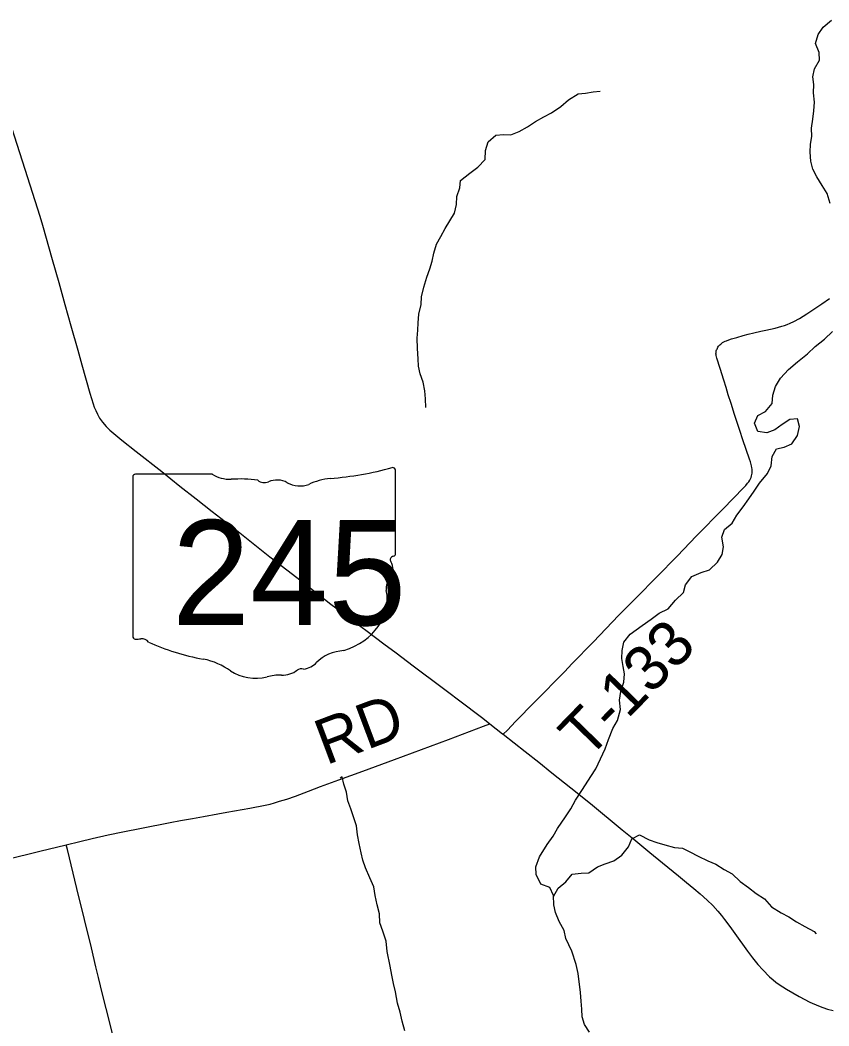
# Model space of a CAD drawing. Extents: x 0 to 1101, y 0 to 440.
# Drawn here: x 844.169 to 845.184, y 374.552 to 375.815 of the extents above; entities that cross this region are included whole.
import ezdxf

# ---------------------------------------------------------------- set-up
doc = ezdxf.new("R2010")
doc.units = 0
for name, color, linetype in [('GM_X_County_Road', 7, 'Continuous'), ('GM_X_County_Road_Text', 7, 'Continuous'), ('GM_X_Minor_River', 7, 'Continuous'), ('GM_X_State_Location', 7, 'Continuous'), ('GM_X_State_Route', 7, 'Continuous'), ('GM_X_State_Shield', 7, 'Continuous'), ('GM_X_Township_Road', 7, 'Continuous'), ('GM_X_Township_Road_Text', 7, 'Continuous')]:
    doc.layers.add(name, color=color, linetype=linetype)

msp = doc.modelspace()

# ---------------------------------------------------------------- linework, layer by layer
at = {"layer": 'GM_X_County_Road'}
for points in [[(844.2269, 374.7791), (844.2439, 374.7832), (844.2596, 374.7871), (844.2795, 374.7916), (844.2978, 374.7953), (844.3215, 374.8), (844.3575, 374.8072), (844.3703, 374.8097), (844.3855, 374.8124), (844.399, 374.8149), (844.4173, 374.8182), (844.4283, 374.82), (844.4571, 374.825), (844.4766, 374.829), (844.4827, 374.8304), (844.4881, 374.8319), (844.4947, 374.8338), (844.5036, 374.8366), (844.5148, 374.8404), (844.5311, 374.8465), (844.5462, 374.8522), (844.5689, 374.8607), (844.5993, 374.8717), (844.6389, 374.8862), (844.7066, 374.9116), (844.7505, 374.9282), (844.7584, 374.9312)], [(843.6675, 374.6391), (843.6723, 374.6421), (843.676, 374.6441), (843.6783, 374.6452), (843.6812, 374.6464), (843.6836, 374.6473), (843.6862, 374.6481), (843.6934, 374.6502), (843.6999, 374.6518), (843.7119, 374.6549), (843.73, 374.6593), (843.7837, 374.6721), (843.8399, 374.6857), (843.8774, 374.6945), (843.9257, 374.7062), (843.9721, 374.7179), (843.9992, 374.7246), (844.0312, 374.7323), (844.0959, 374.7475), (844.1515, 374.7608), (844.1938, 374.771), (844.2269, 374.7791)]]:
    msp.add_lwpolyline(points, dxfattribs=at)
at = {"layer": 'GM_X_Minor_River'}
for points in [[(845.1856, 375.5847), (845.1819, 375.5973), (845.1759, 375.6072), (845.1691, 375.618), (845.1639, 375.6276), (845.1613, 375.6379), (845.1607, 375.6489), (845.1611, 375.6592), (845.1627, 375.6687), (845.1625, 375.679), (845.1641, 375.6904), (845.1653, 375.7011), (845.1662, 375.7118), (845.1648, 375.7236), (845.1652, 375.7339), (845.1638, 375.7438), (845.1662, 375.7537), (845.1724, 375.7647), (845.1721, 375.7742), (845.1672, 375.7857), (845.1707, 375.7967), (845.1769, 375.8062), (845.1873, 375.8149)], [(844.6781, 375.3285), (844.6778, 375.3392), (844.6771, 375.3495), (844.675, 375.3602), (844.6712, 375.3705), (844.669, 375.3801), (844.6684, 375.3896), (844.6677, 375.4026), (844.6675, 375.4155), (844.6683, 375.4254), (844.6684, 375.4349), (844.6693, 375.4456), (844.6724, 375.4578), (844.6729, 375.4673), (844.6756, 375.4795), (844.6796, 375.492), (844.6831, 375.5027), (844.6862, 375.5122), (844.6882, 375.522), (844.6914, 375.5335), (844.6972, 375.5433), (844.7026, 375.5532), (844.7084, 375.563), (844.7142, 375.5725), (844.7165, 375.5835), (844.717, 375.5934), (844.7209, 375.6041), (844.7218, 375.6136), (844.7333, 375.6226), (844.7436, 375.6302), (844.7525, 375.64), (844.7533, 375.6511), (844.7565, 375.6621), (844.7661, 375.6704), (844.7756, 375.6711), (844.7851, 375.671), (844.7954, 375.6751), (844.8057, 375.6807), (844.8157, 375.6875), (844.8264, 375.6935), (844.836, 375.6984), (844.8475, 375.7066), (844.8574, 375.7146), (844.8693, 375.7221), (844.8788, 375.7231), (844.8884, 375.725), (844.8971, 375.7256)], [(844.9186, 374.9351), (844.9226, 374.9492), (844.9215, 374.961), (844.9228, 374.9716), (844.9267, 374.9834), (844.9275, 374.9937), (844.9261, 375.0032), (844.9243, 375.0131), (844.9247, 375.0234), (844.9267, 375.0337), (844.9348, 375.0439), (844.9498, 375.0544), (844.9609, 375.0627), (844.9712, 375.0699), (844.9823, 375.0755), (844.9916, 375.0864), (845.0015, 375.0959), (845.0043, 375.1058), (845.012, 375.116), (845.0238, 375.1212), (845.0342, 375.1245), (845.0445, 375.1343), (845.0503, 375.1438), (845.0519, 375.1533), (845.0497, 375.1655), (845.0533, 375.175), (845.0629, 375.1833), (845.0687, 375.1932), (845.0764, 375.2038), (845.0837, 375.2136), (845.0902, 375.2235), (845.0972, 375.2333), (845.1072, 375.2454), (845.1115, 375.2553), (845.1131, 375.2667), (845.1185, 375.2766), (845.128, 375.2784), (845.1376, 375.2829), (845.1449, 375.2931), (845.1473, 375.3045), (845.1447, 375.3141), (845.1352, 375.3134), (845.1256, 375.307), (845.1161, 375.3002), (845.1061, 375.2965), (845.0951, 375.2981), (845.0906, 375.3085), (845.0949, 375.3183), (845.1045, 375.3232), (845.1129, 375.3334), (845.1138, 375.3437), (845.1173, 375.3547), (845.1235, 375.3653), (845.1335, 375.3759), (845.1446, 375.3857), (845.1573, 375.3959), (845.1669, 375.4049), (845.1787, 375.414), (845.1887, 375.4238)], [(844.8835, 374.5439), (844.8775, 374.5535), (844.8745, 374.5631), (844.8739, 374.5726), (844.8732, 374.5829), (844.8725, 374.5935), (844.8693, 374.6175), (844.8668, 374.629), (844.8616, 374.6458), (844.8541, 374.6615), (844.8519, 374.6714), (844.8455, 374.6829), (844.8411, 374.6943), (844.8389, 374.7039), (844.8386, 374.7157), (844.8337, 374.7256), (844.8224, 374.7299), (844.8168, 374.7418), (844.8161, 374.7517), (844.8208, 374.7642), (844.8304, 374.7797), (844.8381, 374.79), (844.8435, 374.7998), (844.8536, 374.8142), (844.8601, 374.8244), (844.8659, 374.8354), (844.8748, 374.8487), (844.8852, 374.8649), (844.8914, 374.8748), (844.9035, 374.8998), (844.9077, 374.9116), (844.9128, 374.9252), (844.9186, 374.9351)], [(844.652, 374.5457), (844.6487, 374.5575), (844.6458, 374.5689), (844.6425, 374.5804), (844.6403, 374.5945), (844.6377, 374.6052), (844.6355, 374.6155), (844.6334, 374.6269), (844.6297, 374.6452), (844.6283, 374.6582), (844.6242, 374.6708), (844.6205, 374.6811), (844.6199, 374.6925), (844.6173, 374.7036), (844.6147, 374.7154), (844.6129, 374.7265), (844.6081, 374.7376), (844.6025, 374.7502), (844.5991, 374.7597), (844.5969, 374.7693), (844.5944, 374.7807), (844.5926, 374.7918), (844.5912, 374.8032), (844.5878, 374.8131), (844.5841, 374.8242), (844.5804, 374.8342), (844.5786, 374.8452), (844.5753, 374.8552), (844.5731, 374.8647), (844.5708, 374.8628)], [(844.8386, 374.7143), (844.8444, 374.7248), (844.854, 374.7327), (844.8621, 374.7425), (844.8731, 374.7436), (844.883, 374.7438), (844.8937, 374.7514), (844.9033, 374.7551), (844.9144, 374.7592), (844.9243, 374.7663), (844.9324, 374.7765), (844.9367, 374.7868), (844.9463, 374.7916), (844.9584, 374.7854), (844.9683, 374.7819), (844.9781, 374.7791), (844.9903, 374.776), (845.0002, 374.7751), (845.0097, 374.7705), (845.0199, 374.765), (845.032, 374.7592), (845.0423, 374.7549), (845.0525, 374.748), (845.0627, 374.7429), (845.0729, 374.7329), (845.0831, 374.7256), (845.0929, 374.7179), (845.1035, 374.7113), (845.1122, 374.7013), (845.1243, 374.6936), (845.1338, 374.6886), (845.1436, 374.6824), (845.1539, 374.6766), (845.1656, 374.6704), (845.1683, 374.6673)]]:
    msp.add_lwpolyline(points, dxfattribs=at)
at = {"layer": 'GM_X_State_Route'}
msp.add_lwpolyline([(844.1582, 375.6802), (844.1748, 375.6276), (844.1936, 375.5686), (844.1969, 375.5574), (844.2091, 375.5144), (844.2175, 375.4852), (844.2251, 375.4577), (844.2328, 375.4308), (844.2414, 375.4003), (844.2465, 375.3818), (844.2565, 375.3465), (844.2606, 375.3328), (844.2621, 375.3286), (844.2638, 375.3246), (844.2659, 375.3199), (844.2688, 375.3151), (844.2723, 375.3099), (844.2768, 375.3046), (844.2817, 375.2998), (844.2864, 375.2957), (844.2966, 375.2875), (844.3146, 375.2732), (844.3468, 375.2478), (844.3696, 375.2296), (844.3901, 375.2135), (844.4101, 375.1977), (844.4425, 375.1725), (844.4825, 375.141), (844.511, 375.1189), (844.5291, 375.1048), (844.5429, 375.0941), (844.5591, 375.0816), (844.5744, 375.0699), (844.5847, 375.062), (844.6027, 375.0487), (844.6256, 375.0316), (844.6411, 375.0201), (844.6625, 375.0041), (844.6987, 374.9768), (844.7274, 374.955), (844.7413, 374.9445), (844.7496, 374.9381), (844.7584, 374.9312), (844.7746, 374.9186), (844.7754, 374.918), (844.8029, 374.8963), (844.82, 374.8828), (844.8365, 374.8697), (844.8604, 374.8508), (844.885, 374.8309), (844.9247, 374.798), (844.9392, 374.7862), (844.9593, 374.7697), (844.9752, 374.7567), (844.9953, 374.7401), (845.0054, 374.7318), (845.0146, 374.7244), (845.0226, 374.7176), (845.0314, 374.7098), (845.0385, 374.7029), (845.0446, 374.696), (845.0493, 374.6902), (845.0532, 374.6854), (845.0598, 374.6764), (845.066, 374.6679), (845.082, 374.6457), (845.0884, 374.6372), (845.0951, 374.629), (845.1012, 374.622), (845.1096, 374.6135), (845.1141, 374.6095), (845.1176, 374.6066), (845.1217, 374.6036), (845.131, 374.5978), (845.1389, 374.5932), (845.1468, 374.5888), (845.1601, 374.5817), (845.1709, 374.5768), (845.1764, 374.5748), (845.1822, 374.5729), (845.1894, 374.571)], dxfattribs=at)
at = {"layer": 'GM_X_State_Shield'}
for p, q in [((844.6401, 375.1449), (844.6401, 375.2496)), ((844.3105, 375.2412), (844.3105, 375.041)), ((844.4103, 375.2446), (844.3137, 375.2446)), ((844.64, 375.1449), (844.6401, 375.1449))]:
    msp.add_line(p, q, dxfattribs=at)
for centre, major_axis, start_param, end_param in [((844.5227, 375.5174), (0.3495, 0), 4.814394, 5.042369), ((844.6364, 375.25), (0.00367, 0), 6.141152, 7.989035), ((844.3143, 375.2416), (0.00382, 0), 1.712693, 3.28349), ((844.4332, 375.2678), (0.037, 0), 4.042523, 4.731795), ((844.4455, 375.1322), (0.133, 0), 1.404758, 1.657858), ((844.4757, 375.2426), (0.0107, 0), 3.836095, 5.185415), ((844.4914, 375.2195), (0.0222, 0), 0.950623, 2.079405), ((844.5201, 375.2512), (0.0267, 0), 4.081561, 5.145723), ((844.5673, 375.1835), (0.0703, 0), 1.699011, 2.107814), ((844.6362, 375.1445), (0.00393, 0), 5.05454, 6.418171), ((844.6392, 375.1372), (0.00568, 0), 1.883978, 3.671073), ((844.6031, 375.1239), (0.0341, 0), 5.934695, 6.695948), ((844.6532, 375.1011), (0.0248, 0), 2.387724, 3.262537), ((844.5423, 375.0877), (0.0874, 0), 5.101752, 6.440018), ((844.3143, 375.0406), (0.00385, 0), 3.00124, 4.508301), ((844.3149, 375.0611), (0.0294, 0), 4.665946, 4.897461), ((844.3209, 375.0295), (0.0106, 0), 0.519207, 1.627899), ((844.4547, 375.2093), (0.2524, 0), 4.195997, 4.488961), ((844.5791, 374.9848), (0.0479, 0), 1.647645, 2.488434), ((844.3795, 374.9511), (0.079, 0), 0.823519, 1.323587), ((844.5185, 375.0216), (0.0282, 0), 4.937069, 5.64225), ((844.4649, 375.0285), (0.0501, 0), 4.026481, 4.996735), ((844.4975, 375.0135), (0.0267, 0), 4.691044, 5.507374), ((844.5217, 374.9941), (0.00752, 0), 1.147584, 2.315152), ((844.4938, 374.9593), (0.0412, 0), 1.495662, 1.94098)]:
    msp.add_ellipse(centre, major_axis=major_axis, ratio=0.8, start_param=start_param, end_param=end_param, dxfattribs=at)
at = {"layer": 'GM_X_Township_Road'}
for points in [[(844.7754, 374.918), (844.7806, 374.9233), (844.7908, 374.9339), (844.8151, 374.9588), (844.8522, 374.9964), (844.8621, 375.0067), (844.8881, 375.0335), (844.9206, 375.0677), (844.9425, 375.0897), (844.9935, 375.1415), (845.0181, 375.167), (845.0511, 375.2008), (845.0775, 375.228), (845.0798, 375.2306), (845.082, 375.2332), (845.0835, 375.2352), (845.0849, 375.2372), (845.0857, 375.2388), (845.0865, 375.2405), (845.0871, 375.2424), (845.0876, 375.2443), (845.0878, 375.2459), (845.0879, 375.2474), (845.0878, 375.249), (845.0877, 375.2508), (845.0874, 375.2527), (845.0871, 375.255), (845.0865, 375.257), (845.0856, 375.2602), (845.0845, 375.2635), (845.0762, 375.2876), (845.0722, 375.2994), (845.0658, 375.3195), (845.0614, 375.3333), (845.0579, 375.3443), (845.0551, 375.3534), (845.0521, 375.3627), (845.0475, 375.3775), (845.0434, 375.3905), (845.043, 375.3919), (845.0426, 375.3935), (845.0425, 375.3946), (845.0424, 375.3959), (845.0425, 375.3972), (845.0426, 375.3984), (845.0428, 375.3996), (845.0432, 375.4008), (845.0437, 375.4018), (845.0443, 375.4031), (845.0448, 375.4041), (845.0456, 375.4052), (845.0464, 375.4062), (845.0472, 375.4071), (845.0483, 375.4081), (845.0496, 375.4091), (845.0507, 375.4099), (845.0522, 375.4107), (845.0538, 375.4115), (845.0556, 375.4123), (845.0586, 375.4134), (845.0619, 375.4145), (845.0686, 375.4164), (845.0766, 375.4187), (845.0829, 375.4203), (845.09, 375.4221), (845.0988, 375.4241), (845.1049, 375.4255), (845.1109, 375.4268), (845.1169, 375.4282), (845.1252, 375.4304), (845.1284, 375.4313), (845.1316, 375.4325), (845.1356, 375.4341), (845.1401, 375.4362), (845.1471, 375.4401), (845.1565, 375.4461), (845.1751, 375.4586), (845.1849, 375.4652)], [(844.2875, 374.5313), (844.2815, 374.5554), (844.2725, 374.5916), (844.2673, 374.6127), (844.2642, 374.626), (844.2585, 374.6496), (844.2498, 374.6852), (844.2402, 374.7244), (844.2283, 374.7733), (844.2269, 374.7791)]]:
    msp.add_lwpolyline(points, dxfattribs=at)

# ---------------------------------------------------------------- texts
at = {"layer": 'GM_X_County_Road_Text'}
msp.add_text('RD', height=0.05682, rotation=20.6125, dxfattribs=at).set_placement((844.5529, 374.8789))
at = {"layer": 'GM_X_State_Location'}
for s in ['s', 'r']:
    msp.add_text(s, height=0.000189, dxfattribs=at).set_placement((844.4716, 375.1278))
msp.add_text('245', height=0.000189, rotation=0, dxfattribs=at).set_placement((844.4047, 375.114))
at = {"layer": 'GM_X_State_Shield'}
msp.add_text('245', height=0.13184, dxfattribs=at).set_placement((844.3596, 375.0551))
at = {"layer": 'GM_X_Township_Road_Text'}
msp.add_text('T-133', height=0.05682, rotation=45.7845, dxfattribs=at).set_placement((844.8814, 374.8851))

doc.saveas('drawing.dxf')
